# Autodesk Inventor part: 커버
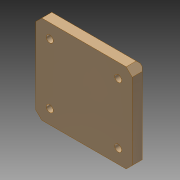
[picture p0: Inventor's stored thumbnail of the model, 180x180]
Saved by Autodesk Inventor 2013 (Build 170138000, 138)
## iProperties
Created: 2023-03
Part Number: 커버
Material: 알루미늄 6061
Document SubType Name: Modeling
Designer: mdu-01
Density: 1 g/cm^3
Author: mdu-01
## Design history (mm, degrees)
sketch "스케치1"
  geometry: L1 (-24, -22)-(24, -22); L2 (24, -22)-(24, 22); L3 (24, 22)-(-24, 22); L4 (-24, 22)-(-24, -22); L5 (-24, -22)-(24, 22); L6 (24, -22)-(-24, 22); 2 further points
  constraints: 12 end point, 2 midpoint, 2 parallel, 1 horizontal, 1 perpendicular, 1 point on line, 1 other
  dimensions: "d2" = 1 distance from line of L4 point (-25, -22)
extrude "돌출1" new body sketch "스케치1" distance "d0" = 6; taper "d1" = 0 deg
hole "구멍1" diameter "d6" = 3.4; stored, may be unused: countersink angle "d10" = 90 deg, drill point angle "d12" = 118 deg; dims "d4" = 7, "d5" = 7, "d7" = 6, "d8" = 6.5, "d9" = 3.4, "d11" = 8
chamfer "모따기1" distance "d13" = 3; stored, may be unused: second distance "d14" = 2, angle "d15" = 45 deg
chamfer "모따기2" distance "d16" = 1; stored, may be unused: second distance "d17" = 2, angle "d18" = 45 deg
node "솔리드1"
mirror "대칭1"
mirror "대칭2"
